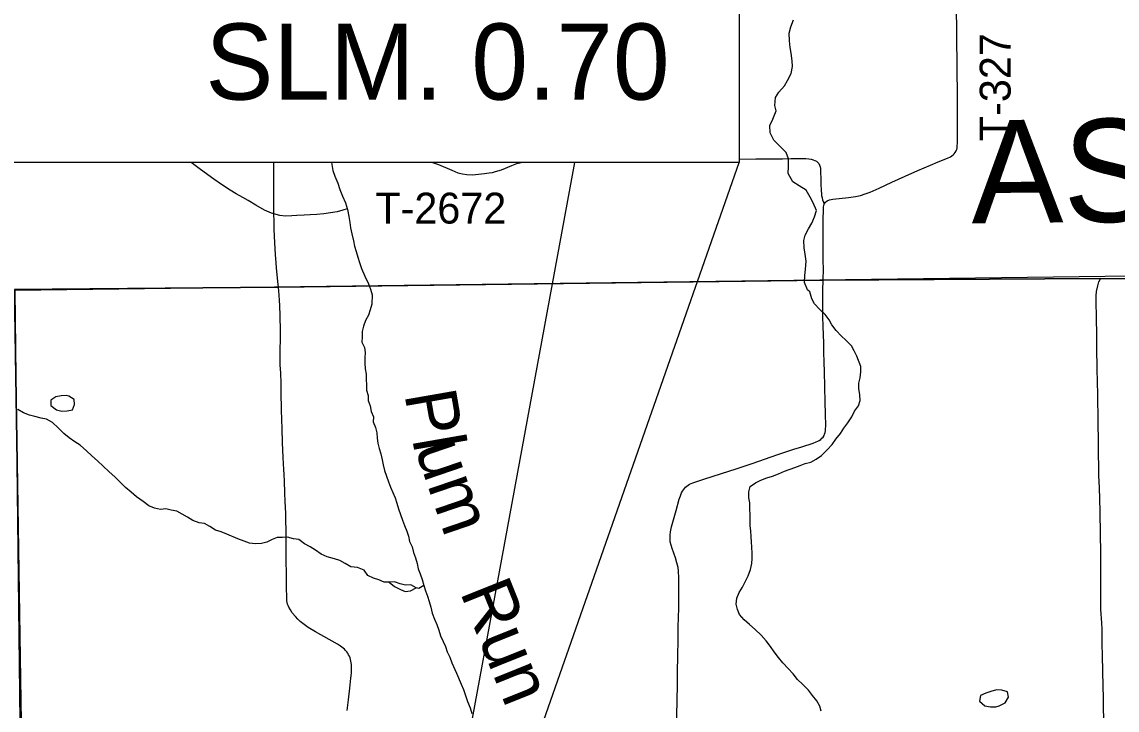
# Model space of a CAD drawing. Extents: x -7.5 to 53.5, y 0 to 22.
# Drawn here: x 4.57 to 6.583, y 18.362 to 19.628 of the extents above; entities that cross this region are included whole.
import ezdxf

# ---------------------------------------------------------------- set-up
doc = ezdxf.new("R2010")
doc.units = 0
for name, color, linetype in [('GM_X_Corporation', 7, 'Continuous'), ('GM_X_County_Road', 7, 'Continuous'), ('GM_X_County_Text', 7, 'Continuous'), ('GM_X_Minor_Lake', 7, 'Continuous'), ('GM_X_Minor_River', 7, 'Continuous'), ('GM_X_Minor_River_Text', 7, 'Continuous'), ('GM_X_Township_Road', 7, 'Continuous'), ('GM_X_Township_Road_Text', 7, 'Continuous'), ('SH_Data', 7, 'Continuous'), ('SH_Text', 7, 'Continuous')]:
    doc.layers.add(name, color=color, linetype=linetype)

msp = doc.modelspace()

# ---------------------------------------------------------------- linework, layer by layer
at = {"layer": 'GM_X_Corporation'}
for points in [[(4.6087, 14.5302), (4.6021, 15.6139), (4.594, 15.8096), (4.5873, 16.3533), (4.5872, 16.3635), (4.5826, 16.8462), (4.5822, 16.8992), (4.577, 17.1178), (4.5749, 17.2575), (4.5771, 17.6201), (4.5718, 18.1276), (4.5696, 18.2604), (4.5565, 19.1354), (5.0411, 19.1401), (6.0424, 19.1527), (6.0433, 19.1527), (6.5522, 19.1561), (7.544, 19.1455), (8.414, 19.1709), (8.5159, 19.1718), (8.9, 19.1887), (8.9, 20.9), (2.1, 20.9), (2.1, 14.1)], [(8.9, 14.1), (8.9, 19.1887), (8.5159, 19.1718), (8.414, 19.1709), (7.544, 19.1455), (6.5522, 19.1561), (6.0433, 19.1527), (6.0424, 19.1527), (5.0411, 19.1401), (4.5565, 19.1354), (4.5696, 18.2604), (4.5718, 18.1276), (4.5771, 17.6201), (4.5749, 17.2575), (4.577, 17.1178), (4.5822, 16.8992), (4.5826, 16.8462), (4.5872, 16.3635), (4.5873, 16.3533), (4.594, 15.8096), (4.6021, 15.6139), (4.6087, 14.5302)]]:
    msp.add_lwpolyline(points, dxfattribs=at)
at = {"layer": 'GM_X_County_Road'}
msp.add_lwpolyline([(5.0413, 19.1396), (5.0403, 19.1504), (5.038, 19.1752), (5.0372, 19.1845), (5.0361, 19.2), (5.0349, 19.2217), (5.0338, 19.2464), (5.0335, 19.2557), (5.0334, 19.2619), (5.0333, 19.2743), (5.0332, 19.2929), (5.0331, 19.3053), (5.0331, 19.3177), (5.0331, 19.3425), (5.0331, 19.3673), (5.0331, 19.3693)], dxfattribs=at)
at = {"layer": 'GM_X_Minor_Lake'}
for points in [[(4.6515, 18.9407), (4.642, 18.9401), (4.6325, 18.9383), (4.623, 18.9319), (4.6229, 18.9224), (4.6334, 18.9144), (4.6433, 18.912), (4.6531, 18.9127), (4.663, 18.9145), (4.6665, 18.9239)], [(4.6665, 18.9239), (4.6662, 18.9334), (4.6564, 18.9396), (4.6515, 18.9407)], [(5.2653, 18.5943), (5.2551, 18.5978), (5.2452, 18.5975), (5.255, 18.5894), (5.2656, 18.584), (5.2746, 18.5805)], [(5.2746, 18.5805), (5.2845, 18.5812), (5.2944, 18.5868), (5.2846, 18.5926), (5.2751, 18.5919), (5.2653, 18.5943)], [(6.3511, 18.3963), (6.3416, 18.393), (6.3321, 18.3889), (6.3305, 18.3787), (6.3403, 18.3703), (6.3505, 18.3679), (6.36, 18.3682), (6.3664, 18.37)], [(6.3664, 18.37), (6.3775, 18.3756), (6.3836, 18.3858), (6.3818, 18.3957), (6.3716, 18.3988), (6.3617, 18.3993), (6.3511, 18.3963)]]:
    msp.add_lwpolyline(points, dxfattribs=at)
at = {"layer": 'GM_X_Minor_River'}
for points in [[(6.0186, 19.131), (6.0141, 19.1351), (6.0087, 19.1483), (6.009, 19.1616), (6.0105, 19.1726), (6.0116, 19.1874), (6.01, 19.2007), (6.0077, 19.2125), (6.0076, 19.2257), (6.0099, 19.2352), (6.0159, 19.2474), (6.0219, 19.2577), (6.0268, 19.2694), (6.0305, 19.2808), (6.0244, 19.2952), (6.019, 19.3051), (6.0114, 19.318), (5.9985, 19.3263), (5.9871, 19.3334), (5.9783, 19.3486), (5.9794, 19.3619), (5.9789, 19.3759), (5.9751, 19.3873), (5.9523, 19.41), (5.9454, 19.4236), (5.9446, 19.4369), (5.9506, 19.4487), (5.9562, 19.4639), (5.9543, 19.4737), (5.955, 19.4885), (5.9614, 19.4984), (5.9716, 19.5102), (5.9776, 19.5201), (5.9843, 19.533), (5.9862, 19.5456), (5.9858, 19.5558), (5.9838, 19.5702), (5.9819, 19.5808), (5.9807, 19.593), (5.9806, 19.607), (5.9836, 19.6188), (5.9881, 19.6313)], [(5.168, 19.2838), (5.16, 19.2814), (5.1494, 19.2787), (5.1373, 19.2767), (5.1248, 19.2748), (5.1123, 19.2736), (5.0998, 19.2728), (5.0888, 19.2724), (5.0755, 19.2716), (5.066, 19.2711), (5.0547, 19.2707), (5.0441, 19.2718), (5.0289, 19.2759), (5.016, 19.2816), (5, 19.2906), (4.9856, 19.2993), (4.9757, 19.305), (4.9639, 19.3117), (4.9529, 19.3185), (4.9366, 19.3287), (4.9229, 19.3382), (4.9115, 19.3465), (4.8959, 19.3582), (4.886, 19.3653), (4.8809, 19.3693)], [(5.1391, 19.3693), (5.1392, 19.3689), (5.1415, 19.3545), (5.1449, 19.3439), (5.1507, 19.331), (5.1541, 19.3193), (5.1591, 19.3075), (5.1645, 19.2947), (5.1683, 19.2829), (5.1707, 19.27), (5.1726, 19.259), (5.1742, 19.2488), (5.1765, 19.2382), (5.1796, 19.2249), (5.1815, 19.2154), (5.1842, 19.2056), (5.1873, 19.1949), (5.1903, 19.1851), (5.1942, 19.1745), (5.2003, 19.1601), (5.2072, 19.1461), (5.211, 19.1362), (5.2137, 19.1255)], [(6.0661, 18.8601), (6.0745, 18.8706), (6.0807, 18.8808), (6.088, 18.8906), (6.0956, 18.9015), (6.1003, 18.9117), (6.1076, 18.9219), (6.1107, 18.9317), (6.1104, 18.9416), (6.1086, 18.9533), (6.1087, 18.9632), (6.111, 18.973), (6.1119, 18.984), (6.1123, 18.9939), (6.1049, 19.0129), (6.1001, 19.0228), (6.0948, 19.0323), (6.0854, 19.0419), (6.0757, 19.0503), (6.0666, 19.0599), (6.0591, 19.0706), (6.0539, 19.0801), (6.0464, 19.0897), (6.0366, 19.0989), (6.0272, 19.1092), (6.022, 19.1187), (6.0186, 19.131)], [(5.2137, 19.1255), (5.2134, 19.1086), (5.2099, 19.0984), (5.2068, 19.0885), (5.2018, 19.0784), (5.1979, 19.0682), (5.1952, 19.0583), (5.1951, 19.0488), (5.1947, 19.0386), (5.1999, 19.0291), (5.2006, 19.0196), (5.2001, 19.0101), (5.2004, 18.9999), (5.2011, 18.99), (5.2025, 18.9798), (5.2028, 18.9699), (5.2035, 18.96), (5.2034, 18.9505), (5.2064, 18.9407), (5.2067, 18.9312), (5.21, 18.9217), (5.2118, 18.911), (5.2163, 18.9015), (5.2158, 18.892), (5.2199, 18.8821), (5.2221, 18.8723), (5.2228, 18.8624), (5.2242, 18.8529), (5.2268, 18.843), (5.2297, 18.8331), (5.2319, 18.8225), (5.2341, 18.813), (5.2367, 18.8027), (5.2404, 18.7921), (5.2437, 18.7822), (5.2474, 18.7723), (5.2515, 18.762), (5.256, 18.7525), (5.2593, 18.7426), (5.2623, 18.7323), (5.2656, 18.7221), (5.2697, 18.7114), (5.273, 18.7015), (5.2775, 18.6912), (5.2804, 18.6817), (5.2826, 18.6719), (5.2871, 18.6623), (5.2896, 18.6521), (5.2937, 18.6422), (5.2963, 18.6315), (5.2985, 18.622), (5.3018, 18.6125), (5.3055, 18.6023), (5.3088, 18.5912), (5.3118, 18.5817), (5.3155, 18.5718), (5.3188, 18.5616), (5.3218, 18.5513), (5.3243, 18.5403), (5.3284, 18.5296), (5.3329, 18.5193), (5.3362, 18.5094), (5.3392, 18.4988), (5.344, 18.4885), (5.3485, 18.479), (5.3514, 18.4695), (5.3567, 18.4596), (5.3604, 18.4493), (5.3685, 18.4303), (5.3775, 18.4097), (5.3816, 18.3998), (5.3856, 18.3888), (5.389, 18.3778), (5.3942, 18.3663), (5.3967, 18.3557)], [(5.2452, 18.5975), (5.2357, 18.5976), (5.2259, 18.6015), (5.2161, 18.6046), (5.2059, 18.6096), (5.1992, 18.6195), (5.1867, 18.6242), (5.1746, 18.6254), (5.1644, 18.6316), (5.1546, 18.637), (5.1444, 18.6401), (5.1308, 18.644), (5.1198, 18.6487), (5.1093, 18.656), (5.0995, 18.6621), (5.0896, 18.6679), (5.0791, 18.676), (5.0689, 18.6772), (5.0583, 18.68), (5.0488, 18.6793), (5.0393, 18.6794), (5.0298, 18.676), (5.0199, 18.6712), (5.0101, 18.6686), (4.9991, 18.6676), (4.9885, 18.6692), (4.9782, 18.6727), (4.9669, 18.6774), (4.9465, 18.6859), (4.9359, 18.6898), (4.9257, 18.6933), (4.9156, 18.6998), (4.9054, 18.7052), (4.8955, 18.7068), (4.8842, 18.7107), (4.8744, 18.7169), (4.8646, 18.7227), (4.8548, 18.7281), (4.8442, 18.73), (4.8343, 18.732), (4.8245, 18.731), (4.8139, 18.7334), (4.8029, 18.738), (4.7927, 18.7457), (4.7807, 18.7541), (4.7709, 18.7629), (4.76, 18.7714), (4.7502, 18.781), (4.7416, 18.7905), (4.7299, 18.8009), (4.7088, 18.8208), (4.6983, 18.8296), (4.6885, 18.8392), (4.6772, 18.8491), (4.6674, 18.8557), (4.6569, 18.8626), (4.6467, 18.871), (4.6366, 18.8813), (4.626, 18.8913), (4.6151, 18.8971), (4.6053, 18.8987), (4.5939, 18.9022), (4.5837, 18.9046), (4.5727, 18.9085), (4.5622, 18.915)], [(6.0389, 18.3601), (6.0367, 18.3696), (6.031, 18.3791), (6.0232, 18.3891), (6.0157, 18.399), (6.0055, 18.409), (5.9957, 18.4185), (5.9879, 18.4288), (5.9785, 18.4384), (5.9687, 18.4491), (5.9605, 18.459), (5.9526, 18.469), (5.9462, 18.4793), (5.938, 18.4896), (5.9286, 18.4999), (5.918, 18.5102), (5.9075, 18.5198), (5.8977, 18.5283), (5.8891, 18.5378), (5.8854, 18.5473), (5.8832, 18.5572), (5.884, 18.5678), (5.8887, 18.5784), (5.8944, 18.5882), (5.9002, 18.5991), (5.9052, 18.6093), (5.9095, 18.6207), (5.9118, 18.6316), (5.9123, 18.6411), (5.9124, 18.6506), (5.9117, 18.6616), (5.9114, 18.6715), (5.9107, 18.681), (5.9101, 18.6916), (5.9086, 18.7011), (5.9087, 18.7113), (5.9084, 18.7212), (5.9078, 18.7322), (5.9078, 18.7432), (5.9064, 18.7527), (5.9065, 18.7637), (5.9085, 18.7735), (5.9184, 18.7799), (5.9283, 18.7847), (5.9393, 18.7892), (5.9499, 18.7925), (5.9606, 18.7965), (5.9716, 18.8014), (5.9906, 18.808), (6.0005, 18.8121), (6.01, 18.8154), (6.0203, 18.818), (6.0302, 18.8236), (6.0401, 18.8303), (6.05, 18.8409), (6.0596, 18.8503), (6.0661, 18.8601)], [(5.3088, 18.5912), (5.2993, 18.586), (5.2944, 18.5868)]]:
    msp.add_lwpolyline(points, dxfattribs=at)
at = {"layer": 'GM_X_Township_Road'}
for points in [[(6.0446, 19.2926), (6.0459, 19.2944), (6.0471, 19.2961), (6.0505, 19.2986), (6.0545, 19.3002), (6.0608, 19.3014), (6.0897, 19.3049), (6.1023, 19.3067), (6.1117, 19.3087), (6.1203, 19.3114), (6.1292, 19.3148), (6.1461, 19.3221), (6.1689, 19.3327), (6.1939, 19.3438), (6.217, 19.3545), (6.2284, 19.3593), (6.2399, 19.3641), (6.2541, 19.3701), (6.2712, 19.3771), (6.2767, 19.3797), (6.2793, 19.3813), (6.2818, 19.3832), (6.2839, 19.3853), (6.2858, 19.3877), (6.2873, 19.3904), (6.2884, 19.3932), (6.2891, 19.3962), (6.2895, 19.3993), (6.2898, 19.4054), (6.2898, 19.4208), (6.2897, 19.4363), (6.2897, 19.4518), (6.2897, 19.4704), (6.2897, 19.5015), (6.2894, 19.5326), (6.289, 19.5543), (6.2885, 19.5916), (6.2886, 19.6195), (6.2876, 19.6692)], [(5.3248, 19.3693), (5.3266, 19.3688), (5.3358, 19.3656), (5.36, 19.3551), (5.371, 19.3504), (5.3799, 19.3481), (5.3877, 19.3469), (5.3977, 19.3467), (5.4035, 19.3472), (5.4091, 19.3479), (5.42, 19.3489), (5.4291, 19.3501), (5.435, 19.3509), (5.4406, 19.3523), (5.4514, 19.3554), (5.4706, 19.3635), (5.4799, 19.3671), (5.4876, 19.3693)], [(5.8885, 19.3755), (5.9189, 19.3757), (5.9486, 19.3761), (5.968, 19.3761), (5.9841, 19.3762), (5.9993, 19.3766), (6.0111, 19.3763), (6.0167, 19.3758), (6.0207, 19.3753), (6.0243, 19.3742), (6.0275, 19.3731), (6.0304, 19.3714), (6.0332, 19.3694), (6.0349, 19.367), (6.0364, 19.3643), (6.0374, 19.3609), (6.038, 19.3582), (6.0382, 19.3549), (6.0382, 19.3516), (6.0384, 19.3393), (6.0388, 19.3273), (6.0391, 19.3199), (6.04, 19.3087), (6.041, 19.304), (6.0419, 19.3002), (6.0432, 19.2961), (6.0446, 19.2926)], [(6.0427, 19.1522), (6.0432, 19.1743), (6.0428, 19.1874), (6.0428, 19.2012), (6.0427, 19.2323), (6.043, 19.2633), (6.0433, 19.2836), (6.0436, 19.2874), (6.044, 19.29), (6.0446, 19.2926)], [(5.7733, 18.329), (5.7743, 18.3787), (5.7749, 18.4098), (5.7753, 18.4284), (5.7758, 18.4657), (5.776, 18.4874), (5.7766, 18.5154), (5.7773, 18.5496), (5.7776, 18.5682), (5.7778, 18.5931), (5.7775, 18.6055), (5.7768, 18.6179), (5.776, 18.6241), (5.7741, 18.6332), (5.7714, 18.6421), (5.765, 18.6596), (5.7632, 18.6656), (5.7619, 18.6717), (5.7613, 18.6778), (5.7613, 18.6841), (5.7621, 18.6902), (5.7642, 18.6993), (5.7724, 18.7293), (5.7784, 18.7503), (5.7803, 18.7562), (5.7827, 18.7619), (5.7842, 18.7647), (5.7858, 18.7673), (5.7877, 18.7698), (5.7898, 18.7721), (5.7921, 18.7741), (5.7948, 18.776), (5.7973, 18.7774), (5.803, 18.78), (5.8089, 18.782), (5.8237, 18.7867), (5.8562, 18.7973), (5.8828, 18.806), (5.9123, 18.8159), (5.9593, 18.8321), (5.9889, 18.8419), (6.0037, 18.8465), (6.0244, 18.8532), (6.0303, 18.8554), (6.0331, 18.8567), (6.0358, 18.8582), (6.0384, 18.8599), (6.0407, 18.862), (6.0427, 18.8643), (6.0444, 18.8669), (6.0456, 18.8698), (6.0464, 18.8727), (6.047, 18.8758), (6.0474, 18.8789), (6.0476, 18.8851), (6.0469, 18.9068), (6.0463, 18.9286), (6.0461, 18.9566), (6.0453, 18.9845), (6.0448, 19.0011), (6.0443, 19.0207), (6.0439, 19.0358), (6.0434, 19.0536), (6.0431, 19.0661), (6.0425, 19.087), (6.0425, 19.1144), (6.0425, 19.1341), (6.0427, 19.1522)], [(6.559, 18.3298), (6.5581, 18.3827), (6.5572, 18.4325), (6.5564, 18.4636), (6.5559, 18.4822), (6.5557, 18.4978), (6.5555, 18.5102), (6.555, 18.5226), (6.5535, 18.5474), (6.5532, 18.5599), (6.5531, 18.5723), (6.5532, 18.5878), (6.5534, 18.6064), (6.5534, 18.622), (6.5534, 18.6531), (6.553, 18.6842), (6.5521, 18.7277), (6.551, 18.7713), (6.5499, 18.793), (6.5496, 18.8021), (6.5494, 18.8141), (6.549, 18.8285), (6.5488, 18.8395), (6.5488, 18.8551), (6.5482, 18.8924), (6.5475, 18.9422), (6.5467, 18.9888), (6.5461, 19.0292), (6.5458, 19.0603), (6.5456, 19.0758), (6.5453, 19.0884), (6.5449, 19.1092), (6.5447, 19.1237), (6.5455, 19.1319), (6.5476, 19.1421), (6.5499, 19.1499), (6.5525, 19.1555)], [(5.1677, 18.3613), (5.1683, 18.3666), (5.17, 18.3812), (5.1725, 18.4027), (5.1747, 18.4208), (5.1757, 18.4302), (5.176, 18.4396), (5.1757, 18.4459), (5.1748, 18.4521), (5.1741, 18.4552), (5.1731, 18.4582), (5.1719, 18.4612), (5.1705, 18.464), (5.1689, 18.4667), (5.167, 18.4693), (5.165, 18.4718), (5.1628, 18.474), (5.1605, 18.4762), (5.1555, 18.48), (5.1501, 18.4833), (5.1094, 18.5061), (5.0961, 18.5142), (5.0885, 18.5194), (5.0814, 18.5253), (5.0769, 18.5295), (5.0727, 18.534), (5.0669, 18.5413), (5.0634, 18.5463), (5.0605, 18.5516), (5.0594, 18.5543), (5.0584, 18.557), (5.0576, 18.5602), (5.0571, 18.5632), (5.0566, 18.5693), (5.0562, 18.5878), (5.056, 18.6126), (5.0559, 18.6374), (5.0558, 18.6495), (5.0557, 18.6633), (5.0557, 18.6706), (5.0556, 18.6798), (5.0548, 18.7242), (5.0539, 18.746), (5.0531, 18.7615), (5.0523, 18.7831), (5.0518, 18.7955), (5.0513, 18.8048), (5.0502, 18.8265), (5.0491, 18.8544), (5.0482, 18.8792), (5.0472, 18.9134), (5.0465, 18.9475), (5.0462, 18.9631), (5.0456, 18.9817), (5.0449, 18.9972), (5.0446, 19.0127), (5.0447, 19.0251), (5.0451, 19.0438), (5.0451, 19.05), (5.045, 19.0593), (5.0445, 19.0873), (5.0439, 19.1059), (5.0435, 19.1151), (5.0426, 19.125), (5.0413, 19.1396)]]:
    msp.add_lwpolyline(points, dxfattribs=at)
at = {"layer": 'SH_Data'}
msp.add_lwpolyline([(8.9, 19.1896), (4.5566, 19.1336), (4.6149, 14.11), (4.6151, 14.1)], dxfattribs=at)
at = {"layer": 'SH_Text'}
for points in [[(4.0742, 19.9368), (5.8885, 19.9368), (5.8885, 19.3693), (4.0742, 19.3693)], [(5.8885, 19.3693), (5.586, 19.3693), (5.2505, 17.5473)]]:
    msp.add_lwpolyline(points, close=True, dxfattribs=at)

# ---------------------------------------------------------------- texts
at = {"layer": 'GM_X_County_Text'}
msp.add_text('ASHLAND COUNTY', height=0.189394, rotation=0.605, dxfattribs=at).set_placement((6.3159, 19.2572))
at = {"layer": 'GM_X_Minor_River_Text'}
for s, rotation, p in [('Pl', 279.8812, (5.2729, 18.9436)), ('um', 288.8809, (5.2918, 18.8438)), ('Run', 291.8808, (5.3744, 18.5797))]:
    msp.add_text(s, height=0.09472, rotation=rotation, dxfattribs=at).set_placement(p)
at = {"layer": 'GM_X_Township_Road_Text'}
for s, rotation, p in [('T-327', 90, (6.3875, 19.4084)), ('T-2672', 359.9991, (5.2196, 19.2568))]:
    msp.add_text(s, height=0.05682, rotation=rotation, dxfattribs=at).set_placement(p)
at = {"layer": 'SH_Text'}
msp.add_text('SLM. 0.70', height=0.14, dxfattribs=at).set_placement((4.9072, 19.4847))

doc.saveas('drawing.dxf')
